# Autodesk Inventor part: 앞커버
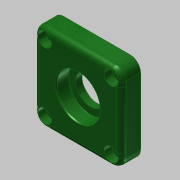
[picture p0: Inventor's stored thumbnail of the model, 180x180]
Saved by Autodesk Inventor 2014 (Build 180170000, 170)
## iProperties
Created: 2018-07
Part Number: 앞커버
Material: 알루미늄 6061
Document SubType Name: Modeling
Designer: mduedu
Density: 1 g/cm^3
Appearance: Smooth - Dark Forest Green
Author: mduedu
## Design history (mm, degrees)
sketch "스케치1"
  geometry: C1 r 16 at (0, 0); 1 further point
  constraints: 1 centre point, 1 coincident
  dimensions: "d0" = 32 diameter of C1
extrude "돌출1" new body sketch "스케치1" distance "d1" = 3; taper "d2" = 0 deg
sketch "스케치2"
  geometry: L1 (-25, -25)-(25, -25); L2 (25, -25)-(25, 25); L3 (25, 25)-(-25, 25); L4 (-25, 25)-(-25, -25); L5 (-25, -25)-(25, 25); L6 (25, -25)-(-25, 25); 1 further point
  constraints: 12 end point, 2 midpoint, 2 parallel, 1 horizontal, 1 perpendicular
  dimensions: "d3" = 50 distance of L3.end L2.end; "d4" = 50 distance of L2.end L1.end
extrude "돌출2" join sketch "스케치2" distance "d5" = 11; taper "d6" = 0 deg
hole "구멍1" diameter "d9" = 25; stored, may be unused: countersink angle "d13" = 90 deg, drill point angle "d15" = 0 deg; dims "d7" = 10, "d8" = 10, "d10" = 6, "d11" = 4, "d12" = 2, "d14" = 3
sketch "스케치3"
  geometry: C1 r 12.5 at (0, 0); 1 further point
  constraints: 1 centre point, 1 coincident
  dimensions: "d16" = 25 diameter of C1
extrude "돌출3" cut sketch "스케치3" distance "d17" = 7.3; taper "d18" = 0 deg
sketch "스케치4"
  geometry: C1 r 8.5 at (0, 0); 1 further point
  constraints: 1 centre point, 1 coincident
  dimensions: "d19" = 17 diameter of C1
extrude "돌출4" cut sketch "스케치4" stored distance "d20" = 7.3; taper "d21" = 0 deg
chamfer "모따기1" distance "d22" = 0.7; stored, may be unused: second distance "d23" = 2, angle "d24" = 30 deg
fillet "모깎기1" dims "d25" = 0.3
fillet "모깎기2" dims "d26" = 3
fillet "모깎기3" dims "d27" = 6
sketch "스케치5"
  geometry: L1 (25, -19)-(25, 19) reference; L2 (19, 25)-(-19, 25) reference; L3 (-25, 19)-(-25, -19) reference; L4 (-19, -25)-(19, -25) reference; C1 r 12.904 at (0, 0) reference; A1 r 6 centre (19, -19) between (19, -25) and (25, -19) reference; A2 r 6 centre (19, 19) between (25, 19) and (19, 25) reference; A3 r 6 centre (-19, 19) between (-19, 25) and (-25, 19) reference; A4 r 6 centre (-19, -19) between (-25, -19) and (-19, -25) reference; 5 further points
  constraints: 4 coincident
hole "구멍2" sketch "스케치5" at (-19, 19), (19, 19), (19, -19), (-19, -19) diameter "d28" = 4.5; stored, may be unused: countersink angle "d32" = 90 deg, drill point angle "d34" = 0 deg; dims "d29" = 6, "d30" = 8, "d31" = 4.6, "d33" = 3
fillet "모깎기4" dims "d35" = 3
chamfer "모따기2" distance "d36" = 1; stored, may be unused: second distance "d37" = 2, angle "d38" = 45 deg
node "솔리드1"
node "투영된 루프1"
